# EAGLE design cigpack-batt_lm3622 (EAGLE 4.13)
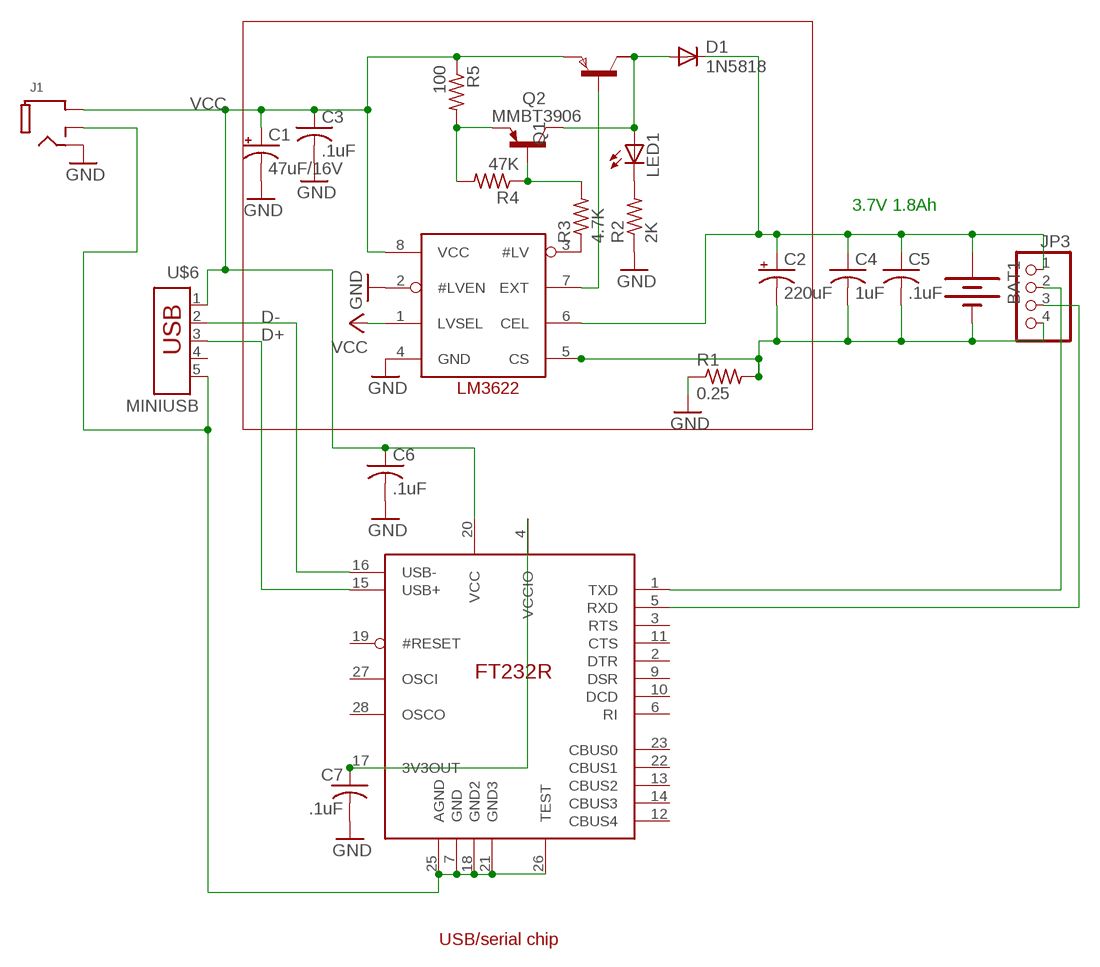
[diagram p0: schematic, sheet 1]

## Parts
BAT1  BATTERY  [LIPOLY-65X34MM]
C1  47uF/16V  CPOL-US153CLV-0605  [153CLV-0605]
C2  220uF  CPOL-US153CLV-0810  [153CLV-0810]
C3  .1uF  C-USC1206  [C1206]
C4  1uF  C-USC3225  [C3225]
C5  .1uF  C-USC1206  [C1206]
C6  .1uF  C-USC1206  [C1206]
C7  .1uF  C-USC1206  [C1206]
D1  1N5818  DIODE-SMB  [SMB]
IC1  LM3622  [SO08]
IC2  FT232R  [TSSOP28]
J1  CLEANAIR_POWERJACK163-2217  [CLEANAIR_5MMJACK]
JP3  PINHD-1X4  [1X04]
LED1  LEDSMT1206  [1206]
Q1  PNPSOT223  [SOT223]
Q2  MMBT3906  MMBT3906LT1SMD  [SOT23-BEC]
R1  0.25  R-US_M1206  [M1206]
R2  2K  R-US_R1206  [R1206]
R3  4.7K  R-US_R1206  [R1206]
R4  47K  R-US_R1206  [R1206]
R5  100  R-US_R1206  [R1206]
U$6  MINIUSB  [UX60A-MB-5SY]

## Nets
D+: IC2.15(USB+) U$6.3
D-: IC2.16(USB-) U$6.2
GND: C1.- C3.2 C6.2 C7.2 IC1.2(#LVEN) IC1.4(GND) J1.RING R1.1 R2.1
N$1: BAT1.- C2.- C4.2 C5.2 IC1.5(CS) JP3.4 R1.2
N$2: IC2.7(GND) IC2.18(GND2) IC2.21(GND3) IC2.25(AGND) IC2.26(TEST) J1.RING_SW U$6.5
N$3: LED1.C R2.2
N$4: IC1.3(#LV) R3.1
N$5: Q2.B R3.2 R4.1
N$6: Q2.E R4.2 R5.2
N$7: D1.A LED1.A Q1.4(C1) Q2.C
N$8: BAT1.+ C2.+ C4.1 C5.1 D1.C IC1.6(CEL) JP3.1
N$9: IC1.7(EXT) Q1.1(B)
N$10: IC2.1(TXD) JP3.2
N$17: C7.1 IC2.4(VCCIO) IC2.17(3V3OUT)
N$41: IC2.5(RXD) JP3.3
VCC: C1.+ C3.1 C6.1 IC1.1(LVSEL) IC1.8(VCC) IC2.20(VCC) J1.TIP Q1.3(E) R5.1 U$6.1
Unconnected: IC2.2(DTR) IC2.3(RTS) IC2.6(RI) IC2.9(DSR) IC2.10(DCD) IC2.11(CTS) IC2.12(CBUS4) IC2.13(CBUS2) IC2.14(CBUS3) IC2.19(#RESET) IC2.22(CBUS1) IC2.23(CBUS0) IC2.27(OSCI) IC2.28(OSCO) Q1.2(C) U$6.4

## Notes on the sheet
- 3.7V 1.8Ah
- USB/serial chip

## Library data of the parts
BAT1 = cleanair:BATTERY: BATTERY
C1 C2 = rcl:CPOL-US: POLARIZED CAPACITOR, American symbol
C3-C7 = rcl:C-US: CAPACITOR, American symbol
D1 = diode:DIODE-: DIODE
IC1 = liion:LM3622
IC2 = ft232:FT232R
J1 = cigpack-batt_lm3622:CLEANAIR_POWERJACK
JP3 = pinhead:PINHD-1X4: PIN HEADER
LED1 = led:LED: LED
Q1 = zetex:PNPSOT223: PNP TRANSISTOR
Q2 = transistor-pnp:MMBT3906*: PNP Transistror
R1-R5 = rcl:R-US_: RESISTOR, American symbol
U$6 = cleanair:MINIUSB

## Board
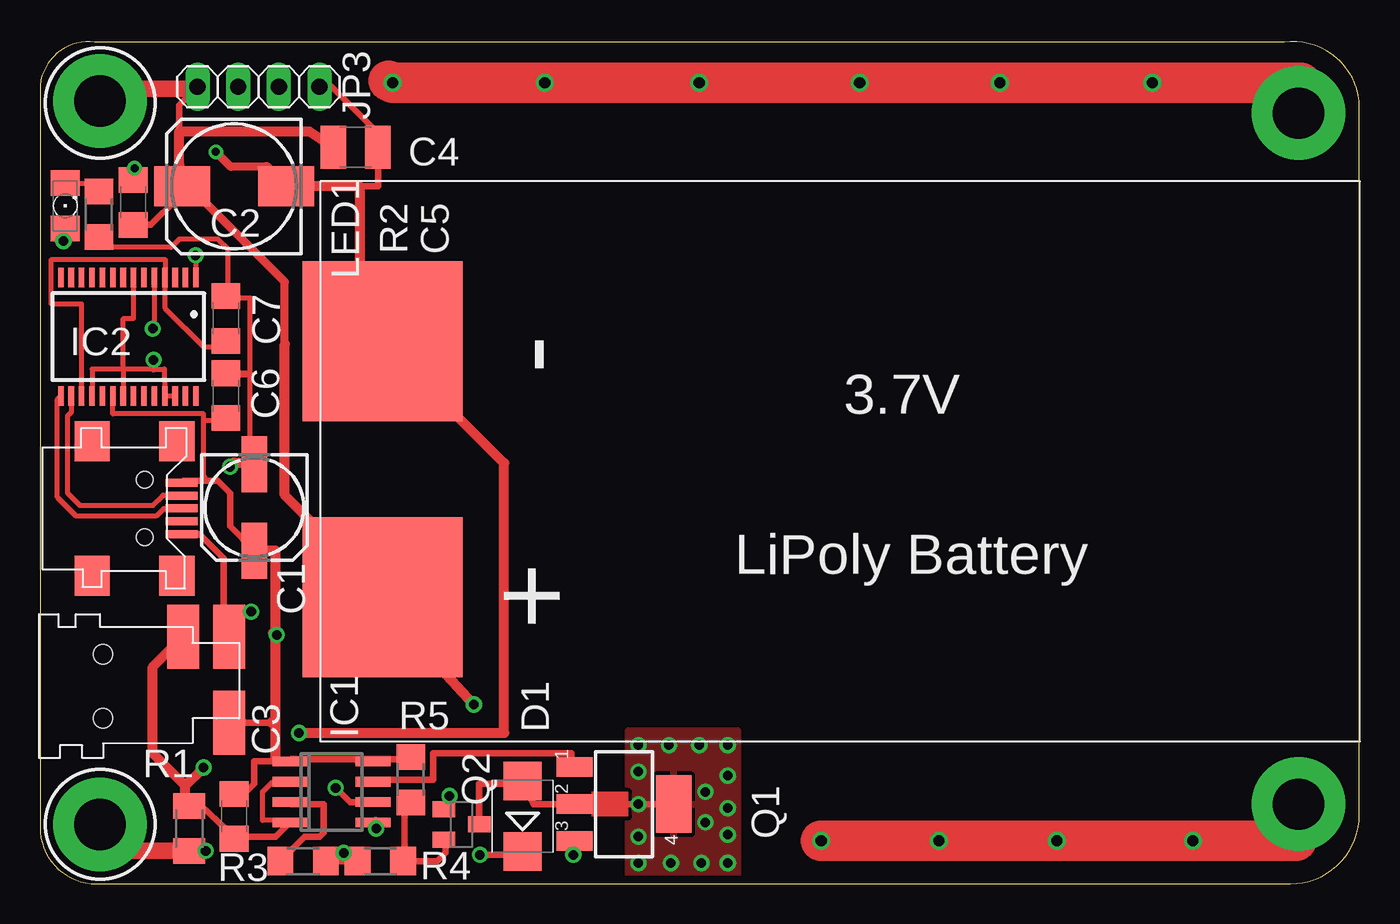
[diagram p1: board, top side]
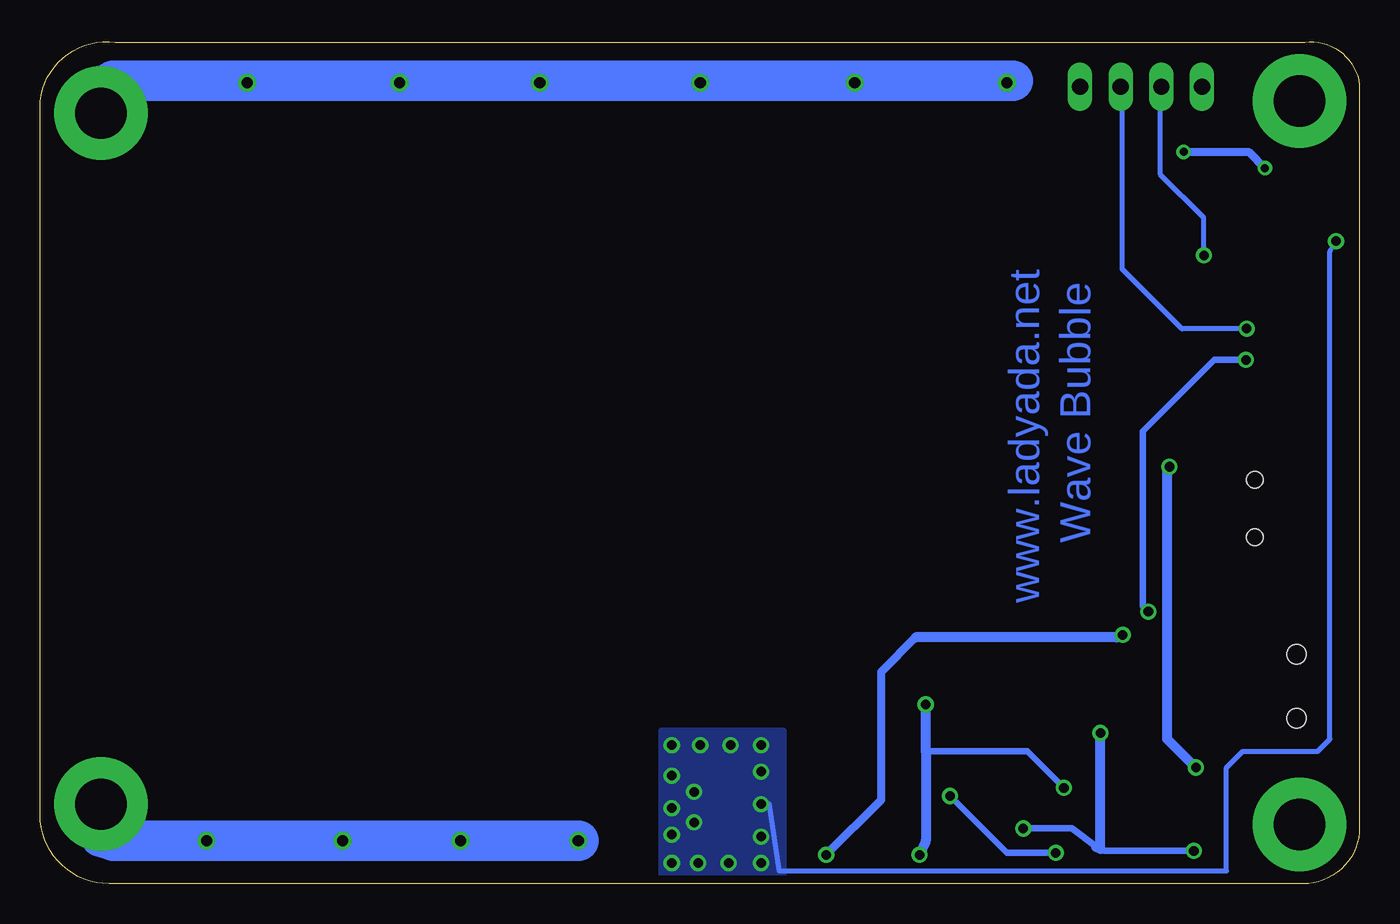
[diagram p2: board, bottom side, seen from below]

Size 82.49 x 52.63 mm. Coordinates in mm from the lower left corner, seen from the top.
Outline: 3.43,52.6 arc90 0,49.93 0,3.52 arc90 3.52,0 78.16,0 arc90 82.49,4.33 82.49,48.9 arc90 77.78,52.6 3.43,52.6
Copper layers (1*16): Top 0.035mm / dielectric 1.5mm / Bottom 0.035mm
Design rules "default": minimum track width 12mil, minimum drill 19mil, track to track 10mil, track to pad 10mil, pad to pad 10mil, via to via 10mil, smd to smd 1mil, copper to edge 20mil, drill to drill 8mil, minimum pad ring 10mil, minimum via ring 8mil, stop-mask expansion 4mil, vias tented up to drill 0mil, thermal gap 10mil

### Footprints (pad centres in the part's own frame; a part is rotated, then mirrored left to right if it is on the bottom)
LIPOLY-65X34MM = smd 10 x 10: + -8,28.11; - 8,28.11
153CLV-0605 = smd 3.5 x 1.6: + 2.7,0; - -2.7,0
153CLV-0810 = smd 3.5 x 2.5: + 3.25,0; - -3.25,0
C1206 = smd 1.6 x 1.8: 1 -1.4,0; 2 1.4,0
C3225 = smd 1.6 x 2.7: 1 -1.4,0; 2 1.4,0
SMB = smd 2.4 x 2.4: A 2.2,0; C -2.2,0
SO08 = smd 0.6 x 2.2: 1 -1.905,-2.6; 2 -0.635,-2.6; 3 0.635,-2.6; 4 1.905,-2.6; 5 1.905,2.6; 6 0.635,2.6; 7 -0.635,2.6; 8 -1.905,2.6
TSSOP28 = smd 0.35 x 1.2: 1 -4.225,-3.7; 2 -3.575,-3.7; 3 -2.925,-3.7; 4 -2.275,-3.7; 5 -1.625,-3.7; 6 -0.975,-3.7; 7 -0.325,-3.7; 8 0.325,-3.7; 9 0.975,-3.7; 10 1.625,-3.7; 11 2.275,-3.7; 12 2.925,-3.7; 13 3.575,-3.7; 14 4.225,-3.7; 15 4.225,3.7; 16 3.575,3.7; 17 2.925,3.7; 18 2.275,3.7; 19 1.625,3.7; 20 0.975,3.7; 21 0.325,3.7; 22 -0.325,3.7; 23 -0.975,3.7; 24 -1.625,3.7; 25 -2.275,3.7; 26 -2.925,3.7; 27 -3.575,3.7; 28 -4.225,3.7
CLEANAIR_5MMJACK = smd 2 x 4: RING -9,-2.596; RING_SW -11.9,-2.6; TIP -11.9,2.8 | hole 1.2: -4,2.5; -4,-1.5
1X04 = drill 1.016 long: 1 -3.81,0; 2 -1.27,0; 3 1.27,0; 4 3.81,0
1206 = smd 1.6 x 1.803: A -1.422,0; C 1.422,0
SOT223 = smd 1.219 x 2.235: 1 -2.311,-3.099; 2 0,-3.099; 3 2.311,-3.099 | smd 3.6 x 2.2: 4 0,3.099
SOT23-BEC = smd 1 x 1.4: B -0.95,-1.1; C 0,1.1; E 0.95,-1.1
M1206 = smd 1.6 x 2: 1 -1.4,0; 2 1.4,0
R1206 = smd 1.6 x 1.803: 1 -1.422,0; 2 1.422,0
UX60A-MB-5SY = smd 0.5 x 2: 1 -1.6,2.3; 2 -0.8,2.3; 3 0,2.3; 4 0.8,2.3; 5 1.6,2.3 | smd 2.5 x 2.2: C1 -4.2,2; C2 -4.2,-3.3; C3 4.2,-3.3; C4 4.2,2 | hole 1.016: -1.8,0; 1.8,0

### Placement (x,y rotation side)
BAT1  49.52,25.9 90 top
C1  13.4,23.52 270 top
C2  12.13,43.59 180 top
C3  12.13,4.22 270 top
C4  19.73,46.02 0 top
C5  5.84,42.58 90 top
C6  11.63,30.5 90 top
C7  11.63,35.33 90 top
D1  30.17,4.22 90 top
IC1  18.23,5.74 270 top
IC2  5.53,34.19 180 top
J1  -0.06,12.85 180 top
JP3  13.66,49.81 0 top
LED1  1.58,42.37 90 top
Q1  36.52,4.98 270 top
Q2  26.36,3.71 270 top
R1  9.34,3.45 270 top
R2  3.68,41.84 90 top
R3  16.45,1.42 0 top
R4  21.28,1.42 0 top
R5  23.18,6.5 270 top
U$6  6.56,23.46 270 top

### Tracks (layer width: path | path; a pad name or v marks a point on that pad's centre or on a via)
19GHZANT  (via drill 0.7, 3.2 pad 5.84)
  Top 0.305: 78.68,3.83 78.81,3.96 | 78.68,3.83 78.55,3.83 78.55,2.69 | 78.68,3.83 v78.68,4.98
  Top 2.54: v48.84,2.69 52.39,2.69 v56.2,2.69 59.89,2.69 v63.57,2.69 67.76,2.69 v72.08,2.69 78.55,2.69
  Bottom 2.54: v48.84,2.69 52.39,2.69 v56.2,2.69 59.89,2.69 v63.57,2.69 67.76,2.69 v72.08,2.69 77.92,2.69 78.68,2.95 v78.68,4.98
800MHZANT  (via drill 0.7, 3.2 pad 5.84)
  Top 0.305: 78.81,50.06 79.44,49.43 v78.68,48.16
  Top 0.406: 73.6,50.19 73.35,50.44 72.97,50.06 v69.54,50.06
  Top 2.54: 21.79,50.19 v22.04,50.06 26.61,50.06 v31.57,50.06 38.04,50.06 v41.22,50.06 46.93,50.06 v51.25,50.06 55.95,50.06 v60.01,50.06 64.84,50.06 v69.54,50.06 78.81,50.06
  Bottom 2.54: v78.68,48.16 78.68,49.81 77.92,50.19 21.66,50.19
D+
  Top 0.305: U$6.3 7.75,23.46 7.31,23.01 2.23,23.01 1.08,24.16 1.08,30.25 1.3,30.47 IC2.15
D-
  Top 0.305: IC2.16 1.97,30.51 1.97,29.49 1.72,29.23 1.72,24.41 2.48,23.65 7.05,23.65 7.69,24.28 8.71,24.28 8.73,24.26 U$6.2
GND  (via drill 0.6)
  Top 0.305: IC1.2 14.55,6.38 13.91,5.74 13.91,3.96 15.63,3.96 | 15.63,3.96 15.69,3.96 | IC1.4 15.63,3.96 | R2.1 3.69,40.28 3.69,39.84 4.01,39.78 8.2,39.78 8.71,40.28 11.12,40.28 11.75,39.65 11.75,36.35 | 11.75,36.35 C7.2 11.75,36.6 13.15,36.6 13.15,31.9 | 11.75,36.35 11.75,36.22 | 13.15,31.9 13.15,31.77 12.01,31.77 C6.2 13.15,31.9 | C1.- 13.15,26.47 13.15,31.9 | 13.15,31.9
  Top 0.406: R1.1 10.11,4.85 12.13,2.95 | 12.13,2.95 C3.2 | IC1.4 14.74,2.95 12.13,2.95 | C1.- 13.4,26.06
  Top 0.61: C1.- 13.4,26.31 12.13,26.31 v11.88,26.06 | 9.09,6.12 7.05,8.15 7.05,13.56 8.9,15.4 8.98,15.4 | R1.1 9.09,4.85 9.09,6.12 | 9.09,6.12 v10.23,7.26 | 8.98,15.4 9.09,15.4 | 8.98,15.4 J1.RING
  Bottom 0.61: v11.88,26.06 12.01,25.93 12.01,9.05 12.02,9.04 12.01,9.04 v10.23,7.26
N$1  (via drill 0.5, 0.6, 3.2 pad 5.84)
  Top 0.406: R1.2 9.21,2.06 v10.36,2.06 | IC1.5 20.96,3.96 21.02,3.96 v21.02,3.45 | 20.01,43.59 21.15,43.59 21.15,46.02 C4.2 21.13,46.11 21.15,46.13 21.15,46.89 18.23,49.81 JP3.4
  Top 0.508: 14.17,44.8 11.93,44.8 v10.99,45.75 | C5.2 5.96,44.65 5.78,44.48 v5.91,44.73
  Top 0.61: 21.28,34.06 21.28,34.03 BAT1.- 29.02,26.29 29.02,9.42 v16.2,9.42 | 21.28,34.06 20.01,34.06 20.01,43.59 C2.- 14.17,44.8 | 21.28,34.06 22.68,34.06
  Top 1.016: 3.5,3.71 3.5,3.96 | 3.5,3.71 v3.75,3.71 | R1.2 3.5,2.05 3.5,3.71
  Bottom 0.406: v10.36,2.06 15.94,2.06 16.45,2.31 17.98,3.45 v21.02,3.45
  Bottom 0.508: v10.99,45.75 6.93,45.75 v5.91,44.73
  Bottom 0.61: 16.45,2.31 16.2,2.18 v16.2,9.42
N$2  (via drill 0.6)
  Top 0.305: 7.94,30.49 IC2.25 7.77,32.16 7.07,32.16 5.15,32.16 | 7.94,30.49 IC2.26 | 7.94,30.49 7.94,30.5 | 5.21,32.16 IC2.21 | 5.21,32.16 5.21,35.33 5.86,35.33 IC2.7 | IC2.18 3.26,32.16 5.15,32.16 | 5.15,32.16 5.21,32.16 | J1.RING_SW 12.1,15.71 12.1,16.89 12.17,16.97 13.2,16.97 v13.2,17
  Top 0.406: U$6.5 9.99,21.86 11.49,20.36 11.49,15.98 11.71,15.75 | J1.RING_SW 11.71,15.44 11.71,15.75 | v7.11,32.74 7.07,32.16 | v13.2,17 13.24,16.97 13.24,16.93 12.9,16.93 11.71,15.75
  Bottom 0.406: v13.2,17 13.54,17.35 13.54,28.28 9.09,32.74 v7.11,32.74
N$3
  Top 0.305: R2.2 3.7,43.39 3.62,43.71 3.83,43.79 LED1.C
N$4
  Top 0.406: R3.1 16.55,2.95 17.47,2.95 17.72,3.2 17.72,4.98 15.69,4.98 15.69,5.04 IC1.3
N$5  (via drill 0.6)
  Top 0.406: 17.47,1.68 R3.2 18.74,1.42 | 18.74,1.42 R4.1 | Q2.B 25.6,5 v25.6,5.49 | v18.99,1.93 18.74,1.68 18.74,1.42
  Bottom 0.406: v25.6,5.49 22.04,1.93 v18.99,1.93
N$6
  Top 0.406: R5.2 22.9,4.72 22.8,4.72 22.8,2.29 R4.2 | R4.2 22.45,1.42 | R4.2 24.83,1.42 25.34,1.93 25.34,2.69 25.32,2.69 Q2.E
N$7  (via drill 0.6)
  Top 0.305: LED1.A 1.47,41.34 v1.47,40.16
  Top 0.406: D1.A 30.84,4.98 Q1.4 | D1.A 29.24,6.25 28.05,6.25 | D1.A 30.17,6.25 27.46,6.25 Q2.C
  Bottom 0.305: v1.47,40.16 1.85,39.52 1.85,9.04 2.61,8.28 7.31,8.28 8.32,7.26 8.32,0.79 36.26,0.79 36.9,4.98
  other vias: 42.99,8.66 41.22,8.66 39.31,8.66 37.41,8.66 42.99,6.76 42.99,4.72 42.99,1.29 42.99,3.07 41.34,1.29 39.44,1.29 37.41,1.29 37.41,4.98 41.6,5.74 41.6,3.83 37.41,7.01 37.41,2.95
  pour Top: 36.77,0.41 36.77,9.55 43.63,9.55 43.63,0.41
  pour Bottom: 43.63,0.41 43.63,9.55 36.01,9.55 36.01,0.41
N$8  (via drill 0.6, 3.2 pad 5.84)
  Top 0.406: D1.C 29.45,1.8 v27.5,1.8 | IC1.6 19.37,5.1 v18.48,5.99 | C2.+ 8.58,42.82 6.93,41.18 C5.1 | JP3.1 8.71,48.67 8.71,47.02
  Top 0.508: C2.+ 9.34,43.59 15.31,37.62 15.31,33.73
  Top 0.61: v27.12,11.2 20.93,17.93 BAT1.+ 21.28,18.03 21.28,18.31 15.31,24.28 15.31,33.73 | C2.+ 8.71,44.93 8.71,47.02 16.83,47.02 C4.1
  Top 1.016: JP3.1 9.72,49.68 4.51,49.68 v3.75,48.92
  Bottom 0.406: v18.48,5.99 20.77,8.28 27.12,8.28
  Bottom 0.61: v27.5,1.8 27.12,2.69 27.12,8.28 v27.12,11.2
N$9
  Top 0.406: IC1.7 20.2,6.5 24.58,6.5 24.58,8.15 33.22,8.15 33.22,7.26 33.39,7.26 Q1.1
N$10  (via drill 0.6)
  Top 0.305: IC2.1 9.76,38.85 v9.72,39.27
  Bottom 0.305: v9.72,39.27 9.75,41.63 12.44,44.32 12.44,49.86 | 12.44,49.92 12.44,49.86 | 12.44,49.86 JP3.2
N$17
  Top 0.305: C7.1 11.75,33.55 10.23,33.55 7.81,35.98 IC2.4 7.81,38.24 7.82,38.25 7.82,39.01 0.7,39.01 0.7,36.22 2.6,36.22 IC2.17
N$41  (via drill 0.6)
  Top 0.305: IC2.5 7.16,37.89 7.18,34.57 v7.05,34.7
  Bottom 0.305: v7.05,34.7 11.09,34.67 14.84,38.42 14.84,49.73 14.85,49.73 JP3.3
VCC  (via drill 0.6)
  Top 0.305: 10.23,25.17 10.23,28.98 | 10.23,28.98 10.23,29.36 4.56,29.36 4.55,29.36 | 10.23,28.98 11.83,28.98 | 11.83,28.98 12,28.98 | 4.55,29.36 4.55,29.35 | IC2.20 4.55,29.36 | 9.09,25.17 9.09,25.16 8.96,25.16 U$6.1 | 11.83,28.98 11.83,29.12 11.64,29.12 C6.1
  Top 0.406: 19.75,7.71 19.75,7.77 22.7,7.77 R5.1 | 19.75,7.71 IC1.8 | C3.1 12.26,5.74 12.9,5.74 13.4,6.25 13.4,7.64 14.72,7.64 IC1.1 arc90 15.69,7.71 15.69,7.77 19.69,7.77 arc-90 19.75,7.71 | 10.29,25.23 10.23,25.17 9.09,25.17 8.97,25.17 | 10.29,25.23 10.23,25.43 | C1.+ 11.88,22.34 11.88,24.41 11.12,25.17 10.36,25.17 10.29,25.23 | J1.TIP 11.86,10.07 14.46,10.07 14.5,10.11
  Top 0.508: Q1.3 33.34,2.59 v33.34,1.8
  Top 0.61: C1.+ 14.72,20.82 14.72,15.67 | 14.72,7.64 14.72,10.11 | 14.72,10.11 14.72,15.67 | 14.72,10.11 14.5,10.11 14.5,10.05 | 14.72,15.67 14.57,15.67 14.69,15.56 v14.8,15.56
  Bottom 0.508: v33.34,1.8 29.91,5.23 29.91,13.23 27.75,15.39
  Bottom 0.61: 27.75,15.39 15.2,15.39 v14.8,15.56
(copper drawn outside any net)
  shapes: Top area x1

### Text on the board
Bottom: Wave Bubble | www.ladyada.net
